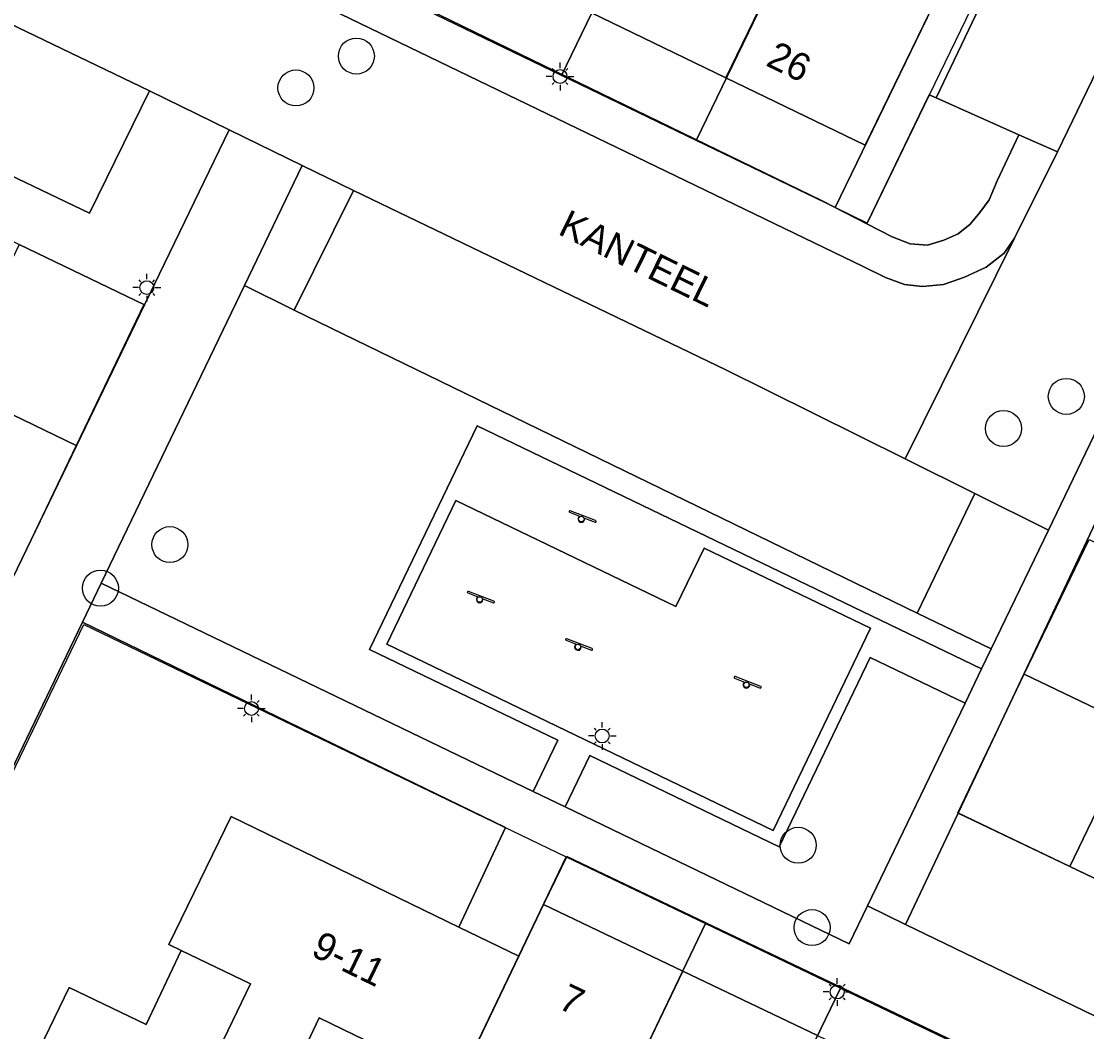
# Model space of a CAD drawing. Extents: x 124901 to 125496, y 515369 to 515789.
# Drawn here: x 125237.15 to 125275.62, y 515460.85 to 515497.31 of the extents above; entities that cross this region are included whole.
import ezdxf

# ---------------------------------------------------------------- set-up
doc = ezdxf.new("R2010")
doc.units = 0
for name, color, linetype in [('Gebouw', 7, 'Continuous'), ('Lichtmast', 7, 'Continuous'), ('Onbegroeid terrein', 7, 'Continuous'), ('Parkeren', 7, 'Continuous'), ('Perceelsgrenzen', 7, 'Continuous'), ('Putten', 7, 'Continuous'), ('Speelvoorziening', 7, 'Continuous'), ('Teksten', 7, 'Continuous'), ('Vegetatie', 7, 'Continuous'), ('Voetpad', 7, 'Continuous'), ('Wegen lokale weg', 7, 'Continuous')]:
    doc.layers.add(name, color=color, linetype=linetype)

msp = doc.modelspace()

# ---------------------------------------------------------------- linework, layer by layer
at = {"layer": 'Gebouw'}
for points in [[(125262.591, 515495.279), (125266.185, 515502.697), (125261.332, 515505.044), (125257.74, 515497.62)], [(125266.185, 515502.697), (125262.591, 515495.279), (125267.62, 515492.84), (125271.22, 515500.26)], [(125286.88, 515465.06), (125287.76, 515466.88), (125277.439, 515471.85), (125275.01, 515466.81), (125282.44, 515463.26), (125285.348, 515461.865)], [(125249.89, 515459.01), (125250.155, 515458.882), (125251.141, 515458.405), (125252.354, 515457.818), (125255.112, 515463.574), (125252.952, 515464.624), (125244.73, 515468.62), (125242.48, 515464), (125242.93, 515463.78), (125245.425, 515462.579), (125244.142, 515459.915), (125246.655, 515458.706), (125247.91, 515461.36), (125250.41, 515460.14)], [(125256.01, 515465.44), (125255.112, 515463.574), (125252.354, 515457.818), (125252.64, 515457.68), (125252.75, 515457.92), (125257.49, 515455.64), (125261.03, 515463.04)], [(125238.88, 515462.45), (125236.751, 515458.043), (125244.969, 515454.073), (125247.108, 515458.486), (125246.655, 515458.706), (125244.142, 515459.915), (125245.425, 515462.579), (125242.93, 515463.78), (125241.66, 515461.11)], [(125265.901, 515460.712), (125261.03, 515463.04), (125257.49, 515455.64), (125256.195, 515452.934), (125261.012, 515450.617), (125262.32, 515453.317)]]:
    msp.add_lwpolyline(points, close=True, dxfattribs=at)
at = {"layer": 'Lichtmast'}
for p, q in [((125256.39, 515495.534), (125256.32, 515495.605)), ((125256.602, 515495.622), (125256.602, 515495.822)), ((125256.814, 515495.534), (125256.885, 515495.606)), ((125256.302, 515495.323), (125256.102, 515495.322)), ((125256.902, 515495.322), (125257.102, 515495.322)), ((125256.39, 515495.11), (125256.318, 515495.039)), ((125256.602, 515495.022), (125256.602, 515494.822)), ((125256.814, 515495.11), (125256.884, 515495.039)), ((125241.474, 515487.917), (125241.404, 515487.988)), ((125241.686, 515488.005), (125241.686, 515488.205)), ((125241.898, 515487.917), (125241.969, 515487.989)), ((125241.386, 515487.706), (125241.186, 515487.705)), ((125241.474, 515487.493), (125241.402, 515487.422)), ((125241.898, 515487.493), (125241.968, 515487.422)), ((125241.986, 515487.705), (125242.186, 515487.705)), ((125241.686, 515487.405), (125241.686, 515487.205)), ((125245.462, 515472.82), (125245.462, 515473.02)), ((125245.162, 515472.521), (125244.962, 515472.52)), ((125245.25, 515472.732), (125245.18, 515472.803)), ((125245.674, 515472.732), (125245.745, 515472.804)), ((125245.762, 515472.52), (125245.962, 515472.52)), ((125245.25, 515472.308), (125245.178, 515472.237)), ((125245.462, 515472.22), (125245.462, 515472.02)), ((125245.674, 515472.308), (125245.744, 515472.237)), ((125257.913, 515471.738), (125257.843, 515471.809)), ((125258.125, 515471.826), (125258.125, 515472.026)), ((125258.337, 515471.738), (125258.408, 515471.81)), ((125257.825, 515471.527), (125257.625, 515471.526)), ((125257.913, 515471.314), (125257.841, 515471.243)), ((125258.337, 515471.314), (125258.407, 515471.243)), ((125258.425, 515471.526), (125258.625, 515471.526)), ((125258.125, 515471.226), (125258.125, 515471.026)), ((125266.395, 515462.499), (125266.325, 515462.57)), ((125266.607, 515462.587), (125266.607, 515462.787)), ((125266.819, 515462.499), (125266.89, 515462.571)), ((125266.307, 515462.288), (125266.107, 515462.287)), ((125266.395, 515462.075), (125266.323, 515462.004)), ((125266.819, 515462.075), (125266.889, 515462.004)), ((125266.907, 515462.287), (125267.107, 515462.287)), ((125266.607, 515461.987), (125266.607, 515461.787))]:
    msp.add_line(p, q, dxfattribs=at)
for centre in [(125256.602, 515495.322), (125241.686, 515487.705), (125245.462, 515472.52), (125258.125, 515471.526), (125266.607, 515462.287)]:
    msp.add_circle(centre, 0.25, dxfattribs=at)
at = {"layer": 'Onbegroeid terrein'}
for points in [[(125226.526, 515510.054), (125247.215, 515500), (125266.064, 515490.84), (125267.251, 515490.227), (125267.68, 515490.005), (125269.932, 515494.666), (125270.182, 515494.553), (125272.778, 515500), (125278.716, 515512.461)], [(125271.22, 515500.26), (125267.62, 515492.84), (125262.591, 515495.279), (125257.74, 515497.62)]]:
    msp.add_lwpolyline(points, dxfattribs=at)
for points in [[(125282.1, 515481.572), (125284.348, 515486.261), (125282.56, 515487.12), (125282.644, 515487.293), (125284.984, 515492.149), (125287.319, 515497.008), (125289.74, 515502.04), (125287.492, 515503.125), (125285.976, 515500), (125277.179, 515481.87), (125270.972, 515468.742), (125275.01, 515466.81), (125277.439, 515471.85), (125279.765, 515476.712)], [(125237.08, 515489.26), (125234.669, 515484.229), (125232.341, 515479.363), (125230.001, 515474.503), (125229.353, 515473.149), (125230.698, 515472.506), (125229.069, 515469.096), (125229.017, 515468.988), (125229.468, 515468.771), (125227.138, 515463.906), (125224.806, 515459.042), (125222.39, 515454), (125225.146, 515452.743), (125232.404, 515468.057), (125241.604, 515487.089)], [(125264.293, 515468.119), (125267.807, 515475.412), (125261.801, 515478.306), (125260.785, 515476.197), (125252.847, 515480.021), (125250.349, 515474.837)], [(125275.8, 515455.98), (125276.637, 515457.734), (125256.848, 515467.182), (125256.01, 515465.44), (125261.03, 515463.04), (125265.901, 515460.712), (125270.78, 515458.38)], [(125250.155, 515458.882), (125249.89, 515459.01), (125250.41, 515460.14), (125247.91, 515461.36), (125246.655, 515458.706), (125247.108, 515458.486), (125244.969, 515454.073), (125242.83, 515449.66), (125240.66, 515445.16), (125242.974, 515444.071)]]:
    msp.add_lwpolyline(points, close=True, dxfattribs=at)
at = {"layer": 'Parkeren'}
for points in [[(125278.716, 515512.461), (125272.778, 515500), (125270.182, 515494.553), (125273.17, 515493.22), (125274.558, 515492.601), (125278.139, 515500), (125283.145, 515510.343)], [(125222.301, 515500), (125221.749, 515498.951), (125239.617, 515490.387), (125241.785, 515494.804), (125230.99, 515500), (125224.058, 515503.337)], [(125249.142, 515491.212), (125247.011, 515486.889), (125269.497, 515475.957), (125271.577, 515480.274), (125269.061, 515481.522), (125264.113, 515483.977), (125262.592, 515484.732)]]:
    msp.add_lwpolyline(points, close=True, dxfattribs=at)
at = {"layer": 'Perceelsgrenzen'}
for points in [[(125278.649, 515512.498), (125272.366, 515499.706), (125267.692, 515490.029), (125266.53, 515490.59), (125261.52, 515493.01), (125256.65, 515495.36), (125251.79, 515497.71), (125246.95, 515500.06), (125242.09, 515502.42), (125237.23, 515504.77), (125232.37, 515507.12), (125226.46, 515509.99), (125237.52, 515533.15), (125242.94, 515544.4), (125246.6, 515551.84), (125248.75, 515556.35), (125253.786, 515553.911), (125258.633, 515551.563), (125263.524, 515549.194), (125268.55, 515546.76), (125266.39, 515542.3), (125286.76, 515532.53)], [(125158.376, 515542.562), (125182.469, 515530.005), (125186.05, 515515.764), (125185.338, 515514.373), (125198.71, 515507.82), (125220.22, 515497.28), (125223.31, 515495.88), (125229.63, 515492.89), (125237.08, 515489.26), (125241.58, 515487.1), (125239.138, 515482.006), (125236.815, 515477.16), (125234.475, 515472.279), (125232.147, 515467.423), (125229.862, 515462.656), (125229.845, 515462.62), (125227.511, 515457.751)], [(125282.44, 515463.26), (125270.96, 515468.75), (125273.36, 515473.76), (125275.7, 515478.62)], [(125227.77, 515451.37), (125239.41, 515475.55), (125256.83, 515467.16), (125261.851, 515464.757), (125266.73, 515462.423), (125271.601, 515460.092)]]:
    msp.add_lwpolyline(points, dxfattribs=at)
for points in [[(125251.79, 515497.71), (125261.52, 515517.78), (125262.94, 515520.87), (125267.8, 515518.52), (125261.34, 515505.04), (125256.65, 515495.36)], [(125256.65, 515495.36), (125261.34, 515505.04), (125267.8, 515518.52), (125272.68, 515516.17), (125271.27, 515513.08), (125266.2, 515502.69), (125261.52, 515493.01)], [(125261.52, 515493.01), (125266.2, 515502.69), (125271.27, 515513.08), (125272.68, 515516.17), (125277.69, 515513.74), (125277.389, 515513.112), (125271.22, 515500.26), (125266.53, 515490.59)], [(125266.53, 515490.59), (125271.22, 515500.26), (125277.389, 515513.112), (125278.649, 515512.498), (125272.366, 515499.706), (125267.692, 515490.029)], [(125216.119, 515487.09), (125213.784, 515482.221), (125213.098, 515482.551), (125215.249, 515486.999), (125217.466, 515491.584), (125220.22, 515497.28), (125223.31, 515495.88), (125229.63, 515492.89), (125237.08, 515489.26), (125241.58, 515487.1), (125239.138, 515482.006), (125218.478, 515492.004)], [(125218.478, 515492.004), (125239.138, 515482.006), (125236.815, 515477.16), (125224.86, 515482.97), (125218.56, 515485.92), (125216.119, 515487.09)], [(125295.87, 515462.95), (125292.74, 515464.44), (125287.76, 515466.88), (125277.42, 515471.81), (125273.36, 515473.76), (125275.7, 515478.62), (125287.19, 515473.14), (125298.21, 515467.81), (125298.17, 515467.726)], [(125256.83, 515467.16), (125249.528, 515451.92), (125251.1, 515451.2), (125246.78, 515442.199), (125244.09, 515443.49), (125240.66, 515445.16), (125227.77, 515451.37), (125239.41, 515475.55)], [(125295.87, 515462.95), (125294.746, 515460.609), (125293.45, 515457.91), (125282.44, 515463.26), (125270.96, 515468.75), (125273.36, 515473.76), (125277.42, 515471.81), (125287.76, 515466.88), (125292.74, 515464.44)], [(125261.851, 515464.757), (125257.49, 515455.64), (125251.34, 515443.02), (125250.159, 515440.578), (125246.78, 515442.199), (125251.1, 515451.2), (125249.528, 515451.92), (125256.83, 515467.16)], [(125266.73, 515462.423), (125255.017, 515438.237), (125252.55, 515439.43), (125250.159, 515440.578), (125251.34, 515443.02), (125257.49, 515455.64), (125261.851, 515464.757)], [(125271.601, 515460.092), (125267.22, 515450.96), (125261.06, 515438.34), (125259.879, 515435.887), (125255.017, 515438.237), (125266.73, 515462.423)]]:
    msp.add_lwpolyline(points, close=True, dxfattribs=at)
at = {"layer": 'Putten'}
for centre in [(125249.25, 515496.06), (125247.07, 515494.91), (125274.88, 515483.78), (125272.61, 515482.62), (125242.52, 515478.43), (125240.01, 515476.86), (125265.2, 515467.58), (125265.7, 515464.61)]:
    msp.add_circle(centre, 0.65, dxfattribs=at)
at = {"layer": 'Speelvoorziening'}
for p, q in [((125256.946, 515479.596), (125257.308, 515479.456)), ((125257.889, 515479.295), (125256.968, 515479.651)), ((125257.488, 515479.386), (125257.868, 515479.239)), ((125253.273, 515476.689), (125253.635, 515476.549)), ((125254.216, 515476.388), (125253.295, 515476.744)), ((125253.815, 515476.479), (125254.195, 515476.332)), ((125256.821, 515474.979), (125257.183, 515474.839)), ((125257.764, 515474.678), (125256.843, 515475.034)), ((125257.363, 515474.769), (125257.743, 515474.622)), ((125262.905, 515473.613), (125263.267, 515473.473)), ((125263.848, 515473.312), (125262.927, 515473.668)), ((125263.447, 515473.403), (125263.827, 515473.256))]:
    msp.add_line(p, q, dxfattribs=at)
for centre in [(125257.373, 515479.356), (125253.7, 515476.449), (125257.248, 515474.739), (125263.332, 515473.373)]:
    msp.add_circle(centre, 0.1, dxfattribs=at)
for centre, radius, start, end in [((125256.957, 515479.624), 0.0297, 68.8387, 248.8387), ((125257.373, 515479.356), 0.119, 123.05, 14.6275), ((125257.878, 515479.267), 0.0297, 248.8387, 68.8387), ((125253.284, 515476.717), 0.0297, 68.8387, 248.8387), ((125253.7, 515476.449), 0.119, 123.05, 14.6275), ((125254.205, 515476.36), 0.0297, 248.8387, 68.8387), ((125256.832, 515475.007), 0.0297, 68.8387, 248.8387), ((125257.248, 515474.739), 0.119, 123.05, 14.6275), ((125257.753, 515474.65), 0.0297, 248.8387, 68.8387), ((125262.916, 515473.641), 0.0297, 68.8387, 248.8387), ((125263.332, 515473.373), 0.119, 123.05, 14.6275), ((125263.837, 515473.284), 0.0297, 248.8387, 68.8387)]:
    msp.add_arc(centre, radius, start, end, dxfattribs=at)
at = {"layer": 'Vegetatie'}
for points in [[(125220.89, 515496.95), (125223.31, 515495.88), (125229.63, 515492.89), (125237.08, 515489.26), (125241.604, 515487.089), (125244.656, 515493.402), (125241.785, 515494.804), (125239.617, 515490.387), (125221.749, 515498.951)], [(125273.17, 515493.22), (125270.182, 515494.553), (125269.932, 515494.666), (125267.68, 515490.005), (125268.594, 515489.532), (125269.246, 515489.286), (125269.865, 515489.234), (125270.452, 515489.418), (125270.973, 515489.65), (125271.412, 515489.996), (125271.758, 515490.411), (125272.093, 515490.875), (125272.386, 515491.553)], [(125247.011, 515486.889), (125249.142, 515491.212), (125247.293, 515492.115), (125245.207, 515487.78)], [(125245.207, 515487.78), (125240.039, 515477.039), (125255.631, 515469.527), (125256.522, 515471.376), (125249.725, 515474.65), (125253.611, 515482.717), (125271.823, 515473.943), (125272.172, 515474.668), (125269.497, 515475.957), (125247.011, 515486.889)], [(125271.577, 515480.274), (125269.497, 515475.957), (125272.172, 515474.668), (125274.237, 515478.954)], [(125232.44, 515449.12), (125234.618, 515453.628), (125236.751, 515458.043), (125238.88, 515462.45), (125241.66, 515461.11), (125242.93, 515463.78), (125242.48, 515464), (125244.73, 515468.62), (125252.952, 515464.624), (125254.634, 515468.225), (125239.361, 515475.629), (125227.747, 515451.465)], [(125267.703, 515465.392), (125271.228, 515472.708), (125267.804, 515474.358), (125264.513, 515467.526), (125257.681, 515470.817), (125256.79, 515468.969), (125267.046, 515464.028)], [(125284.283, 515459.757), (125291.709, 515456.205), (125292.768, 515458.316), (125290.355, 515459.47), (125285.348, 515461.865), (125282.44, 515463.26), (125275.01, 515466.81), (125270.972, 515468.742), (125269.073, 515464.726), (125280.176, 515459.354), (125281.076, 515461.272)]]:
    msp.add_lwpolyline(points, close=True, dxfattribs=at)
at = {"layer": 'Voetpad'}
for points in [[(125243.68, 515500), (125267.544, 515488.461), (125268.356, 515488.069), (125269.041, 515487.812), (125269.69, 515487.742), (125270.445, 515487.819), (125270.762, 515487.928), (125271.205, 515488.081), (125271.982, 515488.438), (125272.63, 515488.95), (125273.014, 515489.489), (125274.558, 515492.601), (125273.17, 515493.22), (125272.386, 515491.553), (125272.093, 515490.875), (125271.758, 515490.411), (125271.412, 515489.996), (125270.973, 515489.65), (125270.452, 515489.418), (125269.865, 515489.234), (125269.246, 515489.286), (125268.594, 515489.532), (125267.68, 515490.005), (125267.251, 515490.227), (125266.064, 515490.84), (125247.215, 515500)], [(125227.747, 515451.465), (125239.361, 515475.629), (125240.039, 515477.039), (125245.207, 515487.78), (125247.293, 515492.115), (125244.656, 515493.402), (125241.604, 515487.089), (125232.404, 515468.057), (125225.146, 515452.743)], [(125281.24, 515493.513), (125274.237, 515478.954), (125272.172, 515474.668), (125271.823, 515473.943), (125271.228, 515472.708), (125267.703, 515465.392), (125269.073, 515464.726), (125270.972, 515468.742), (125277.179, 515481.87)]]:
    msp.add_lwpolyline(points, dxfattribs=at)
for points in [[(125256.522, 515471.376), (125255.631, 515469.527), (125256.79, 515468.969), (125257.681, 515470.817), (125264.513, 515467.526), (125267.804, 515474.358), (125271.228, 515472.708), (125271.823, 515473.943), (125253.611, 515482.717), (125249.725, 515474.65)], [(125267.807, 515475.412), (125264.293, 515468.119), (125250.349, 515474.837), (125252.847, 515480.021), (125260.785, 515476.197), (125261.801, 515478.306)], [(125282.021, 515455.164), (125283.764, 515458.703), (125284.283, 515459.757), (125281.076, 515461.272), (125280.176, 515459.354), (125269.073, 515464.726), (125267.703, 515465.392), (125267.046, 515464.028), (125256.79, 515468.969), (125255.631, 515469.527), (125240.039, 515477.039), (125239.361, 515475.629), (125254.634, 515468.225), (125252.952, 515464.624), (125255.112, 515463.574), (125256.01, 515465.44), (125256.848, 515467.182), (125276.637, 515457.734)]]:
    msp.add_lwpolyline(points, close=True, dxfattribs=at)
at = {"layer": 'Wegen lokale weg'}
for points in [[(125230.99, 515500), (125241.785, 515494.804), (125244.656, 515493.402), (125247.293, 515492.115), (125249.142, 515491.212), (125262.592, 515484.732), (125264.113, 515483.977), (125269.061, 515481.522), (125273.014, 515489.489), (125272.63, 515488.95), (125271.982, 515488.438), (125271.205, 515488.081), (125270.762, 515487.928), (125270.445, 515487.819), (125269.69, 515487.742), (125269.041, 515487.812), (125268.356, 515488.069), (125267.544, 515488.461), (125243.68, 515500), (125242.758, 515500.446), (125215.942, 515513.474)], [(125278.139, 515500), (125274.558, 515492.601), (125273.014, 515489.489), (125269.061, 515481.522), (125271.577, 515480.274), (125274.237, 515478.954), (125281.24, 515493.513)]]:
    msp.add_lwpolyline(points, dxfattribs=at)

# ---------------------------------------------------------------- texts
at = {"layer": 'Teksten'}
for s, rotation, p in [('26', 334.1, (125263.993, 515495.736)), ('KANTEEL', 333.9, (125256.488, 515489.65)), ('9-11', 334, (125247.57, 515463.621)), ('7', 334.4, (125256.486, 515461.723))]:
    msp.add_text(s, height=1, rotation=rotation, dxfattribs=at).set_placement(p)

doc.saveas('drawing.dxf')
